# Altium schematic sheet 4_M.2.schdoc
size 431 x 309 mm; Symbol: Sheet-Symbol_A4; Device: Sheet-Symbol_A4; Company: EasyEDA.com; Drawed: EasyEDA Pro; Reviewed: EasyEDA Pro; Version: V0.1; Page Size: A4; @Project Name: CM4-Nvme-NAS-main; @Page Count: 6; @Update Date: 2023-05-19; @Create Date: 2023-04-28; @Schematic Name: RaspberryPiNVMeNAS; Part Number: JLCPCB-002; @Page No: 3; @Page Name: M.2
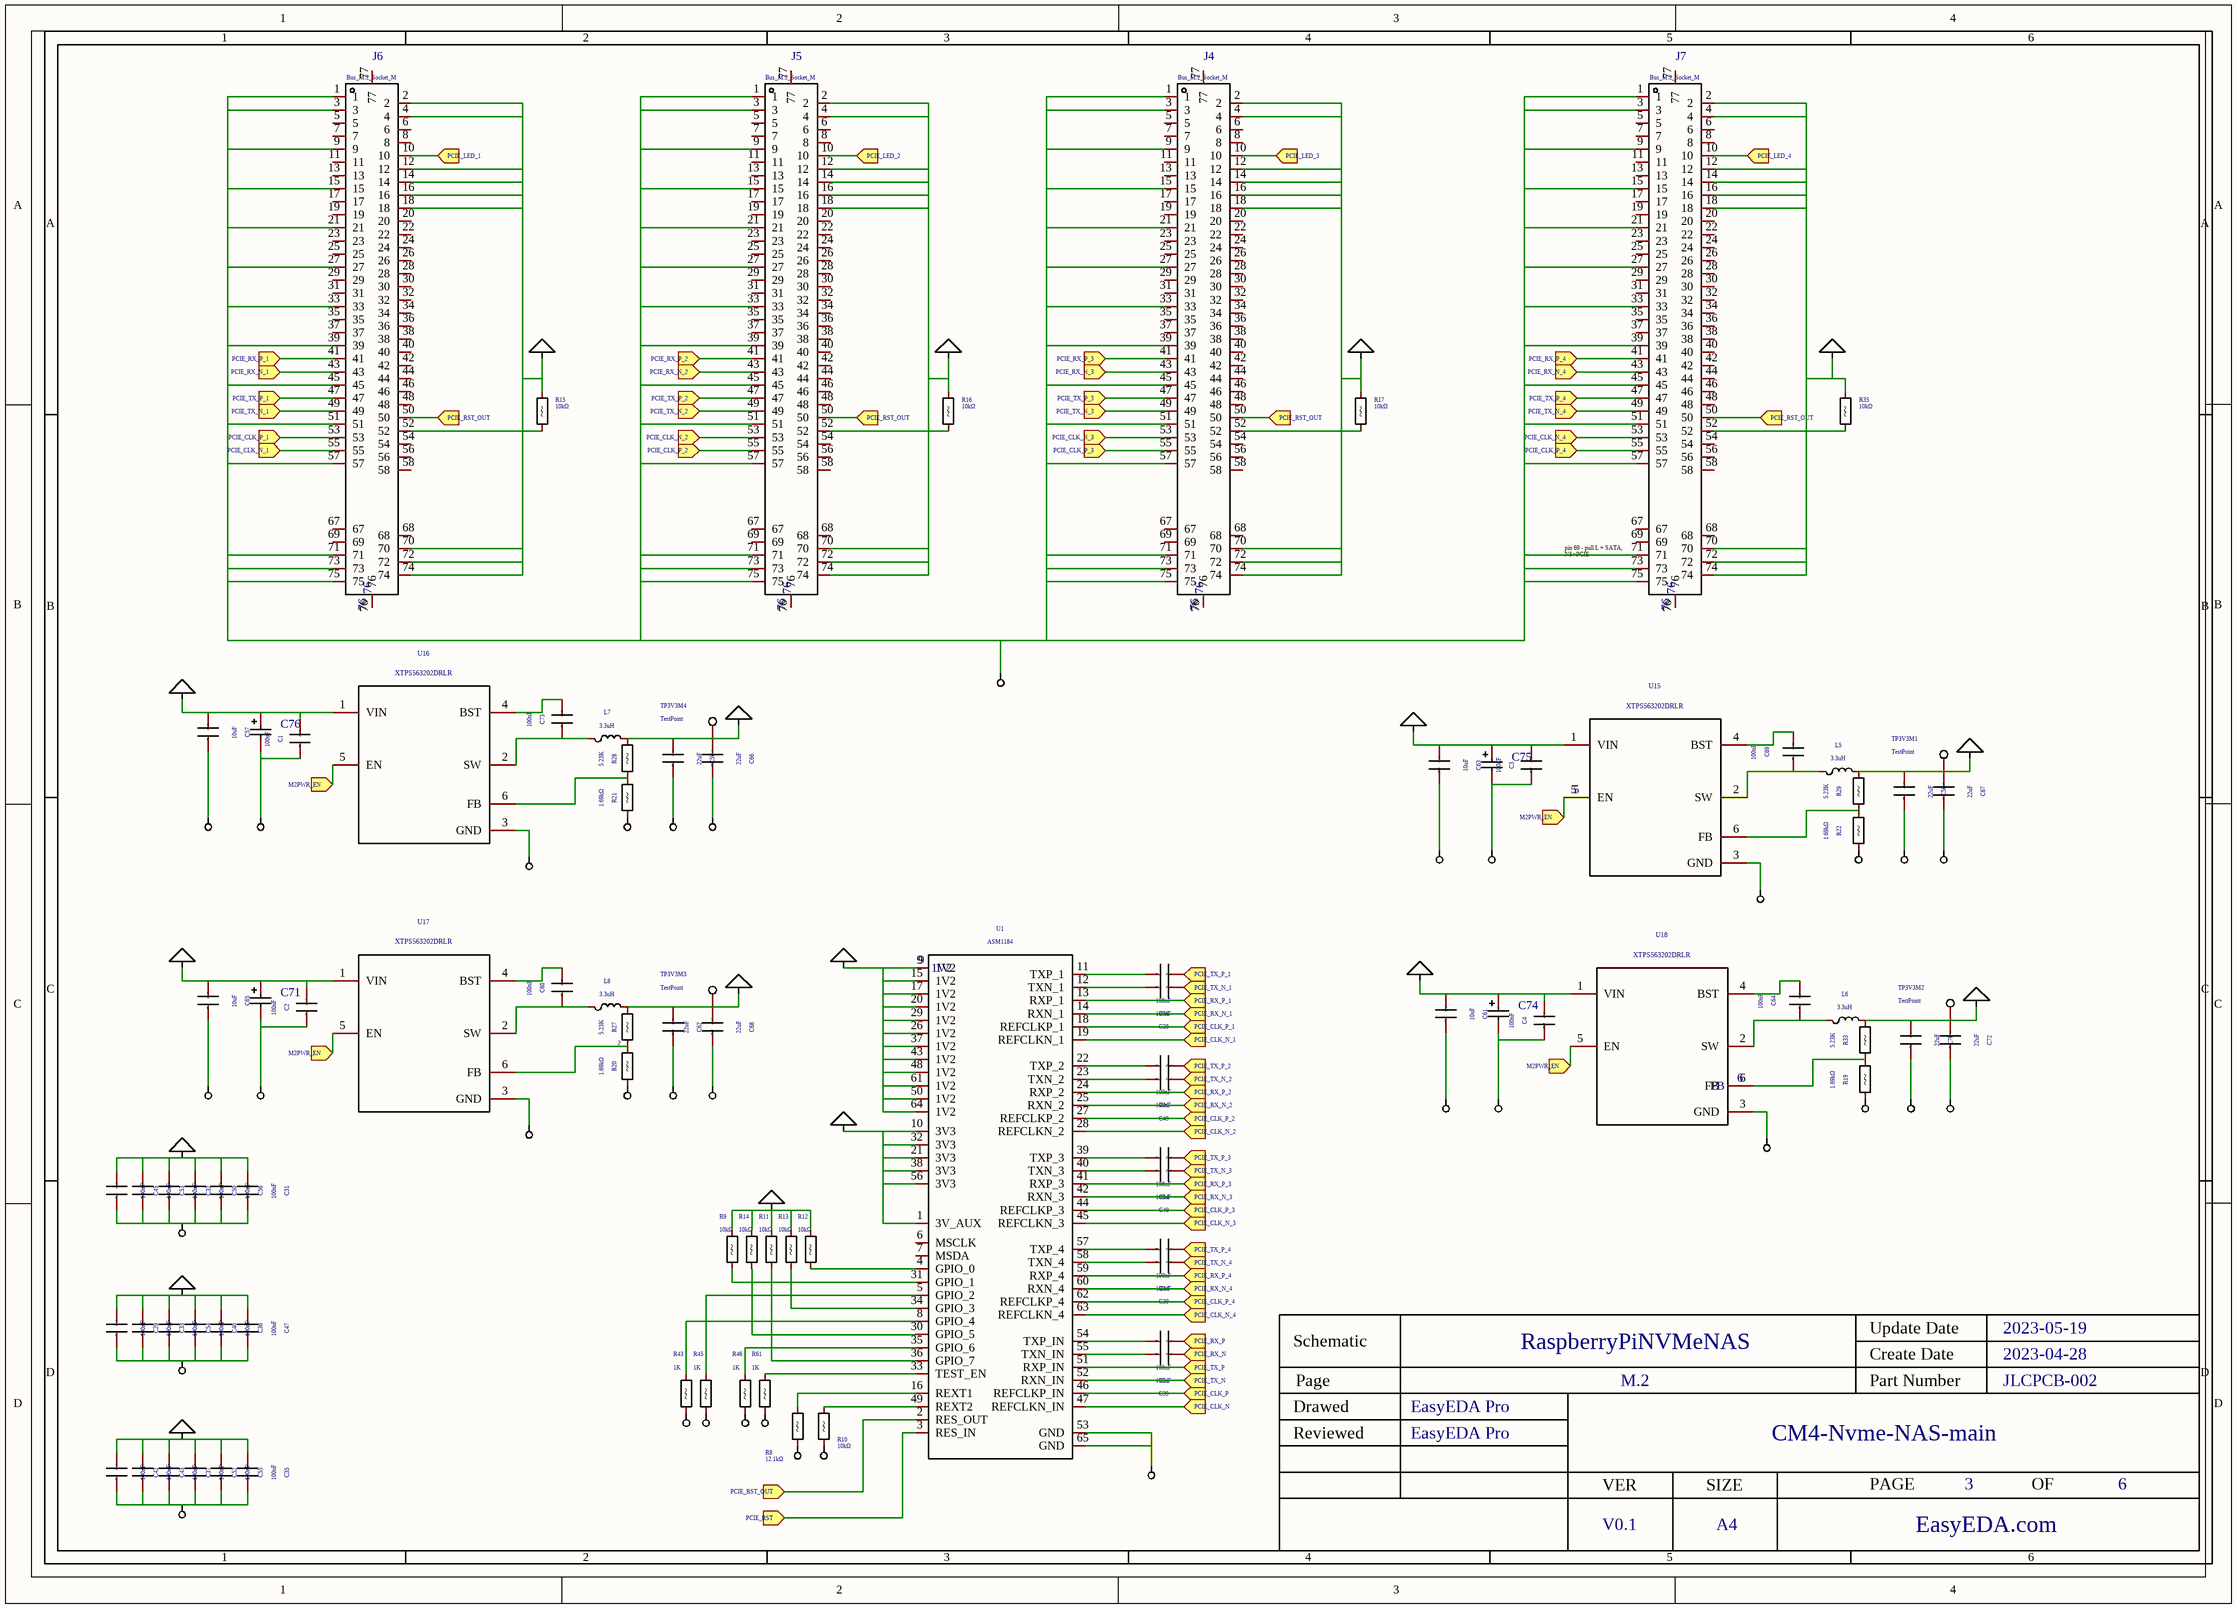
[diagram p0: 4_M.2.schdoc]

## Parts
C1  100nF  [C0402]
C2  100nF  [C0402]
C3  100nF  [C0402]
C4  100nF  [C0402]
C29  100nF  [C0402]
C30  100nF  [C0402]
C31  100nF  [C0402]
C32  100nF  [C0402]
C33  100nF  [C0402]
C34  100nF  [C0402]
C35  100nF  [C0402]
C36  100nF  [C0402]
C37  100nF  [C0402]
C38  100nF  [C0402]
C39  100nF  [C0402]
C40  100nF  [C0402]
C41  100nF  [C0402]
C42  100nF  [C0402]
C43  100nF  [C0402]
C44  100nF  [C0402]
C45  100nF  [C0402]
C46  100nF  [C0402]
C47  100nF  [C0402]
C48  100nF  [C0402]
C49  100nF  [C0402]
C50  100nF  [C0402]
C51  100nF  [C0402]
C52  100nF  [C0402]
C53  100nF  [C0402]
C54  100nF  [C0402]
C55  100nF  [C0402]
C56  100nF  [C0402]
C57  10uF  [C0805]
C58  22uF  [C0805]
C59  22uF  [C0805]
C60  100nF  [C0402]
C61  10uF  [C0805]
C62  22uF  [C0805]
C63  10uF  [C0805]
C64  100nF  [C0402]
C65  10uF  [C0805]
C66  22uF  [C0805]
C67  22uF  [C0805]
C68  22uF  [C0805]
C69  100nF  [C0402]
C70  22uF  [C0805]
C71  TAJA106K016RNJ  [CAP-SMD_L3.2-W1.6-RD-C7171]  (value not drawn)
C72  22uF  [C0805]
C73  100nF  [C0402]
C74  TAJA106K016RNJ  [CAP-SMD_L3.2-W1.6-RD-C7171]  (value not drawn)
C75  TAJA106K016RNJ  [CAP-SMD_L3.2-W1.6-RD-C7171]  (value not drawn)
C76  TAJA106K016RNJ  [CAP-SMD_L3.2-W1.6-RD-C7171]  (value not drawn)
J4  value Bus_M.2_Socket_M  NAME: 76  [PCIE-SMD_75P-P0.50_1-2199230-5]  (hidden comment: 1-2199230-5)
J5  value Bus_M.2_Socket_M  NAME: 76  [PCIE-SMD_75P-P0.50_1-2199230-5]  (hidden comment: 1-2199230-5)
J6  value Bus_M.2_Socket_M  NAME: 76  [PCIE-SMD_75P-P0.50_1-2199230-5]  (hidden comment: 1-2199230-5)
J7  value Bus_M.2_Socket_M  NAME: 76  [PCIE-SMD_75P-P0.50_1-2199230-5]  (hidden comment: 1-2199230-5)
L5  value 3.3uH  [Inductor_SMD:L_Vishay_IHLP-1212]  (hidden comment: Device_L)
L6  value 3.3uH  [Inductor_SMD:L_Vishay_IHLP-1212]  (hidden comment: Device_L)
L7  value 3.3uH  [Inductor_SMD:L_Vishay_IHLP-1212]  (hidden comment: Device_L)
L8  value 3.3uH  [Inductor_SMD:L_Vishay_IHLP-1212]  (hidden comment: Device_L)
R8  12.1kΩ  [R0402]
R9  10kΩ  [R0402]
R10  10kΩ  [R0402]
R11  10kΩ  [R0402]
R12  10kΩ  [R0402]
R13  10kΩ  [R0402]
R14  10kΩ  [R0402]
R15  10kΩ  [R0402]
R16  10kΩ  [R0402]
R17  10kΩ  [R0402]
R19  1.69kΩ  [R0402]
R20  1.69kΩ  [R0402]
R21  1.69kΩ  [R0402]
R22  1.69kΩ  [R0402]
R27  value 5.23K  NAME: ~  [Resistor_SMD:R_0402_1005Metric]  (hidden comment: Device_R)
R28  value 5.23K  [Resistor_SMD:R_0402_1005Metric]  (hidden comment: Device_R)
R29  value 5.23K  [Resistor_SMD:R_0402_1005Metric]  (hidden comment: Device_R)
R33  value 5.23K  [Resistor_SMD:R_0402_1005Metric]  (hidden comment: Device_R)
R35  10kΩ  [R0402]
R43  value 1K  [Resistor_SMD:R_0402_1005Metric]  (hidden comment: Device_R)
R45  value 1K  [Resistor_SMD:R_0402_1005Metric]  (hidden comment: Device_R)
R46  value 1K  [Resistor_SMD:R_0402_1005Metric]  (hidden comment: Device_R)
R61  value 1K  [Resistor_SMD:R_0402_1005Metric]  (hidden comment: Device_R)
TP3V3M1  value TestPoint  [TestPoint:TestPoint_Pad_D1.0mm]  (hidden comment: Connector_TestPoint)
TP3V3M2  value TestPoint  [TestPoint:TestPoint_Pad_D1.0mm]  (hidden comment: Connector_TestPoint)
TP3V3M3  value TestPoint  [TestPoint:TestPoint_Pad_D1.0mm]  (hidden comment: Connector_TestPoint)
TP3V3M4  value TestPoint  [TestPoint:TestPoint_Pad_D1.0mm]  (hidden comment: Connector_TestPoint)
U1  value ASM1184  NAME: 1V2  NUMBER: 9  [Package_DFN_QFN:QFN-64-1EP_9x9mm_P0.5mm_EP5.2x5.2mm]  (hidden comment: ASM1184_ASM1184)
U15  value XTPS563202DRLR  NUMBER: 5  [SOT-563-6_L1.6-W1.2-P0.5-LS1.6-BR]  (hidden comment: TPS563202DRLR)
U16  value XTPS563202DRLR  [SOT-563-6_L1.6-W1.2-P0.5-LS1.6-BR]  (hidden comment: TPS563202DRLR)
U17  value XTPS563202DRLR  [SOT-563-6_L1.6-W1.2-P0.5-LS1.6-BR]  (hidden comment: TPS563202DRLR)
U18  value XTPS563202DRLR  NAME: FB  NUMBER: 6  [SOT-563-6_L1.6-W1.2-P0.5-LS1.6-BR]  (hidden comment: TPS563202DRLR)

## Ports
M2PWR_EN (in), PCIE_CLK_N (in), PCIE_CLK_N_1 (in), PCIE_CLK_N_2 (in), PCIE_CLK_N_3 (in), PCIE_CLK_N_4 (in), PCIE_CLK_P (in), PCIE_CLK_P_1 (in), PCIE_CLK_P_2 (in), PCIE_CLK_P_3 (in), PCIE_CLK_P_4 (in), PCIE_LED_1 (in), PCIE_LED_2 (in), PCIE_LED_3 (in), PCIE_LED_4 (in), PCIE_RST (in), PCIE_RST_OUT (in), PCIE_RX_N (in), PCIE_RX_N_1 (in), PCIE_RX_N_2 (in), PCIE_RX_N_3 (in), PCIE_RX_N_4 (in), PCIE_RX_P (in), PCIE_RX_P_1 (in), PCIE_RX_P_2 (in), PCIE_RX_P_3 (in), PCIE_RX_P_4 (in), PCIE_TX_N (in), PCIE_TX_N_1 (in), PCIE_TX_N_2 (in), PCIE_TX_N_3 (in), PCIE_TX_N_4 (in), PCIE_TX_P (in), PCIE_TX_P_1 (in), PCIE_TX_P_2 (in), PCIE_TX_P_3 (in), PCIE_TX_P_4 (in)

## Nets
+1V2: U1.9(1V2) U1.15(1V2) U1.17(1V2) U1.20(1V2) U1.26(1V2) U1.29(1V2) U1.37(1V2) U1.43(1V2) U1.48(1V2) U1.50(1V2) U1.61(1V2) U1.64(1V2)
+3.3VA: U1.1(3V_AUX) U1.10(3V3) U1.21(3V3) U1.32(3V3) U1.38(3V3) U1.56(3V3)
+12V: C4.1 C61.1 C74.1 U18.1(VIN)
GND: C1.2 C2.2 C4.2 C57.2 C61.2 C62.2 C65.2 C66.2 C68.2 C70.2 C71.2 C72.2 C74.2 C76.2 R8.2 R10.2 R19.2 R20.2 R43.2 R45.2 R46.2 R61.2 U15.3(GND) U16.3(GND) U17.3(GND) U18.3(GND)
POWER_3.3M1: C58.1 C67.1 J6.2 J6.4 J6.12 J6.14 J6.16 J6.18 J6.70 J6.72 J6.74 L5.2 R15.1 R29.1 TP3V3M1.1
POWER_3.3M2: C70.1 C72.1 J5.2 J5.4 J5.12 J5.14 J5.16 J5.18 J5.70 J5.72 J5.74 L6.2 R16.1 R33.1 TP3V3M2.1
POWER_3.3M3: C62.1 C68.1 J4.2 J4.4 J4.12 J4.14 J4.16 J4.18 J4.70 J4.72 J4.74 L8.2 R17.1 R27.1 TP3V3M3.1
POWER_3.3M4: C59.1 C66.1 J7.2 J7.4 J7.12 J7.14 J7.16 J7.18 J7.70 J7.72 J7.74 L7.2 R28.1 R35.1 TP3V3M4.1
POWER_+1V2: C29.1 C31.1 C32.1 C33.1 C36.1 C40.1 C45.1 C47.1 C50.1 C53.1 C54.1 C56.1
POWER_+3.3VA: C35.1 C37.1 C42.1 C43.1 C52.1 C55.1 R9.1 R11.1 R12.1 R13.1 R14.1
POWER_+12V: C1.1 C2.1 C3.1 C57.1 C63.1 C65.1 C71.1 C75.1 C76.1 U15.1(VIN) U16.1(VIN) U17.1(VIN)
POWER_GND: C3.2 C29.2 C31.2 C32.2 C33.2 C35.2 C36.2 C37.2 C40.2 C42.2 C43.2 C45.2 C47.2 C50.2 C52.2 C53.2 C54.2 C55.2 C56.2 C58.2 C59.2 C63.2 C67.2 C75.2 J4.1 J4.3 J4.9 J4.15 J4.21 J4.27 J4.33 J4.39 J4.45 J4.51 J4.57 J4.71 J4.73 J4.75 J5.1 J5.3 J5.9 J5.15 J5.21 J5.27 J5.33 J5.39 J5.45 J5.51 J5.57 J5.71 J5.73 J5.75 J6.1 J6.3 J6.9 J6.15 J6.21 J6.27 J6.33 J6.39 J6.45 J6.51 J6.57 J6.71 J6.73 J6.75 J7.1 J7.3 J7.9 J7.15 J7.21 J7.27 J7.33 J7.39 J7.45 J7.51 J7.57 J7.71 J7.73 J7.75 R21.2 R22.2 U1.53(GND) U1.65(GND)
M2PWR_EN: U15.5(EN) U16.5(EN) U17.5(EN) U18.5(EN) ; port M2PWR_EN
PCIE_CLK_N: U1.47(REFCLKN_IN) ; port PCIE_CLK_N
PCIE_CLK_N_1: J6.55 U1.19(REFCLKN_1) ; port PCIE_CLK_N_1
PCIE_CLK_N_2: J5.53 U1.28(REFCLKN_2) ; port PCIE_CLK_N_2
PCIE_CLK_N_3: J4.53 U1.45(REFCLKN_3) ; port PCIE_CLK_N_3
PCIE_CLK_N_4: J7.53 U1.63(REFCLKN_4) ; port PCIE_CLK_N_4
PCIE_CLK_P: U1.46(REFCLKP_IN) ; port PCIE_CLK_P
PCIE_CLK_P_1: J6.53 U1.18(REFCLKP_1) ; port PCIE_CLK_P_1
PCIE_CLK_P_2: J5.55 U1.27(REFCLKP_2) ; port PCIE_CLK_P_2
PCIE_CLK_P_3: J4.55 U1.44(REFCLKP_3) ; port PCIE_CLK_P_3
PCIE_CLK_P_4: J7.55 U1.62(REFCLKP_4) ; port PCIE_CLK_P_4
PCIE_LED_1: J6.10 ; port PCIE_LED_1
PCIE_LED_2: J5.10 ; port PCIE_LED_2
PCIE_LED_3: J4.10 ; port PCIE_LED_3
PCIE_LED_4: J7.10 ; port PCIE_LED_4
PCIE_RST: U1.3(RES_IN) ; port PCIE_RST
PCIE_RST_OUT: J4.50 J5.50 J6.50 J7.50 U1.2(RES_OUT) ; port PCIE_RST_OUT
PCIE_RX_N: C39.1 ; port PCIE_RX_N
PCIE_RX_N_1: J6.43 U1.14(RXN_1) ; port PCIE_RX_N_1
PCIE_RX_N_2: J5.43 U1.25(RXN_2) ; port PCIE_RX_N_2
PCIE_RX_N_3: J4.43 U1.42(RXN_3) ; port PCIE_RX_N_3
PCIE_RX_N_4: J7.43 U1.60(RXN_4) ; port PCIE_RX_N_4
PCIE_RX_P: C51.1 ; port PCIE_RX_P
PCIE_RX_P_1: J6.41 U1.13(RXP_1) ; port PCIE_RX_P_1
PCIE_RX_P_2: J5.41 U1.24(RXP_2) ; port PCIE_RX_P_2
PCIE_RX_P_3: J4.41 U1.41(RXP_3) ; port PCIE_RX_P_3
PCIE_RX_P_4: J7.41 U1.59(RXP_4) ; port PCIE_RX_P_4
PCIE_TX_N: U1.52(RXN_IN) ; port PCIE_TX_N
PCIE_TX_N_1: C38.1 J6.49 ; port PCIE_TX_N_1
PCIE_TX_N_2: C49.1 J5.49 ; port PCIE_TX_N_2
PCIE_TX_N_3: C48.1 J4.49 ; port PCIE_TX_N_3
PCIE_TX_N_4: C30.1 J7.49 ; port PCIE_TX_N_4
PCIE_TX_P: U1.51(RXP_IN) ; port PCIE_TX_P
PCIE_TX_P_1: C46.1 J6.47 ; port PCIE_TX_P_1
PCIE_TX_P_2: C41.1 J5.47 ; port PCIE_TX_P_2
PCIE_TX_P_3: C34.1 J4.47 ; port PCIE_TX_P_3
PCIE_TX_P_4: C44.1 J7.47 ; port PCIE_TX_P_4
NetC30_2: C30.2 U1.58(TXN_4)
NetC34_2: C34.2 U1.39(TXP_3)
NetC38_2: C38.2 U1.12(TXN_1)
NetC39_2: C39.2 U1.55(TXN_IN)
NetC41_2: C41.2 U1.22(TXP_2)
NetC44_2: C44.2 U1.57(TXP_4)
NetC46_2: C46.2 U1.11(TXP_1)
NetC48_2: C48.2 U1.40(TXN_3)
NetC49_2: C49.2 U1.23(TXN_2)
NetC51_2: C51.2 U1.54(TXP_IN)
NetC60_1: C60.1 U17.4(BST)
NetC60_2: C60.2 L8.1 U17.2(SW)
NetC64_1: C64.1 U18.4(BST)
NetC64_2: C64.2 L6.1 U18.2(SW)
NetC69_1: C69.1 U15.4(BST)
NetC69_2: C69.2 L5.1 U15.2(SW)
NetC73_1: C73.1 U16.4(BST)
NetC73_2: C73.2 L7.1 U16.2(SW)
NetJ4_52: J4.52 R17.2
NetJ5_52: J5.52 R16.2
NetJ6_52: J6.52 R15.2
NetJ7_52: J7.52 R35.2
NetR8_1: R8.1 U1.16(REXT1)
NetR9_2: R9.2 U1.31(GPIO_1)
NetR10_1: R10.1 U1.49(REXT2)
NetR11_2: R11.2 U1.36(GPIO_7)
NetR12_2: R12.2 U1.4(GPIO_0)
NetR13_2: R13.2 U1.34(GPIO_3)
NetR14_2: R14.2 U1.30(GPIO_5)
NetR19_1: R19.1 R33.2 U18.6(FB)
NetR20_1: R20.1 R27.2 U17.6(FB)
NetR21_1: R21.1 R28.2 U16.6(FB)
NetR22_1: R22.1 R29.2 U15.6(FB)
NetR43_1: R43.1 U1.8(GPIO_4)
NetR45_1: R45.1 U1.5(GPIO_2)
NetR46_1: R46.1 U1.35(GPIO_6)
NetR61_1: R61.1 U1.33(TEST_EN)

Not connected (* = marked no-connect by the designer): J4 5 6 7 8 11 13 17 19 20 22 23 24 25 26 28 29 30 31 32 34 35 36 37 38 40 42 44 46 48 54 56 58 67 68 69 76 77; J5 5 6 7 8 11 13 17 19 20 22 23 24 25 26 28 29 30 31 32 34 35 36 37 38 40 42 44 46 48 54 56 58 67 68 69 76 77; J6 5 6 7 8 11 13 17 19 20 22 23 24 25 26 28 29 30 31 32 34 35 36 37 38 40 42 44 46 48 54 56 58 67 68 69 76 77; J7 5 6 7 8 11 13 17 19 20 22 23 24 25 26 28 29 30 31 32 34 35 36 37 38 40 42 44 46 48 54 56 58 67 68 69 76 77; U1 6(MSCLK) 7(MSDA)

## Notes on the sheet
- (near J7) pin 69 - pull L = SATA,
  NS=PCIE

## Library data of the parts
C1-C4 C29-C56 C60 C64 C69 C73 = CL05B104KO5NNNC: Capacitance: Tolerance:±10% Tolerance:±10% Voltage Rated: Temperature Coefficient:; Manufacturer: SAMSUNG(三星); Add into BOM: yes; Tolerance: ±10%; Origin Footprint: C_0402_1005Metric
C57 C61 C63 C65 = CL21A106KAYNNNE_C15850: Capacitance: Tolerance:±10% Tolerance:±10% Voltage Rated: Temperature Coefficient:; Manufacturer: SAMSUNG(三星); Add into BOM: yes; Tolerance: ±10%; Origin Footprint: C_0805_2012Metric
C58 C59 C66 C67 C70 C72 = GRM21BR60J226ME39L: Capacitance: Tolerance:±20% Tolerance:±20% Voltage Rated: Temperature Coefficient:; Manufacturer: muRata(村田); Add into BOM: yes; Tolerance: ±20%; Origin Footprint: C_0805_2012Metric
C62 C68 = GRM21BR60J226ME39L: Capacitance: Tolerance:±20% Tolerance:±20% Voltage Rated: Temperature Coefficient:; Manufacturer: muRata(村田); Add into BOM: yes; Tolerance: ±20%; Origin Footprint: C_0805_2012Metric; NUMBER: 2; Pin Type: IN
C71 C74-C76 = TAJA106K016RNJ: Capacitance: Tolerance:±10% Tolerance:±10% Rated Voltage: Equivalent Series Resistance(ESR):3Ω@100kHz Operating Temperature:-55℃~+125℃ Operating Temperature:-55℃~+125℃; Manufacturer: Kyocera AVX; Name: 10uF; Add into BOM: yes; Value: 10uF; Tolerance: ±10%; Origin Footprint: C_0805_2012Metric
J4-J7 = 1-2199230-5: Connector Type:M.2 Pitch:0.5mm Number of Pins:67 Mounting Style:Surface Mount Height Above Board:4.2mm Operating Temperature Range:- Operating Temperature Range:-; Manufacturer: TE Connectivity(美国泰科); Add into BOM: yes; Connector Type: M.2; Pitch: 0.5mm; Origin Footprint: 1-2199230-6
L5-L8 = Device_L: Add into BOM: yes; Origin Footprint: L_Vishay_IHLP-1212
R8 = RC0402FR-0712K1L: Type:Thick Film Resistors Resistance: Tolerance:±1% Tolerance:±1% Power(Watts): Temperature Coefficient:±100ppm/℃ Temperature Coefficient:±100ppm/℃ Overload Voltage (Max): Operating Temperature Range:-55℃~+155℃ Operating Temperature Range:-55℃~+155℃; Manufacturer: YAGEO(国巨); Add into BOM: yes; Tolerance: ±1%; Origin Footprint: R_0402_1005Metric
R9-R17 R35 = 0402WGF1002TCE: Type:Thick Film Resistors Resistance: Tolerance:±1% Tolerance:±1% Power(Watts): Temperature Coefficient:±100ppm/℃ Temperature Coefficient:±100ppm/℃ Overload Voltage (Max): Operating Temperature Range:-55℃~+155℃ Operating Temperature Range:-55℃~+155℃; Manufacturer: UNI-ROYAL(厚声); Add into BOM: yes; Tolerance: ±1%; Origin Footprint: R_0402_1005Metric
R19-R22 = CR0402FF1691G: Type:Thick Film Resistors Resistance: Tolerance:±1% Tolerance:±1% Power(Watts): Temperature Coefficient:±200ppm/℃ Temperature Coefficient:±200ppm/℃ Overload Voltage (Max): Operating Temperature Range:-55℃~+125℃ Operating Temperature Range:-55℃~+125℃; Manufacturer: LIZ(丽智电子); Add into BOM: yes; Tolerance: ±1%; Origin Footprint: R_0402_1005Metric
R27 = Device_R: Add into BOM: yes; Origin Footprint: R_0402_1005Metric; NUMBER: 2; Pin Type: IN
R28 R29 R33 R43 R45 R46 R61 = Device_R: Add into BOM: yes; Origin Footprint: R_0402_1005Metric
TP3V3M1-TP3V3M4 = Connector_TestPoint: Add into BOM: yes; Origin Footprint: TestPoint_Pad_D1.0mm
U1 = ASM1184_ASM1184: Add into BOM: yes; Origin Footprint: QFN-64-1EP_9x9mm_P0.5mm_EP5.2x5.2mm; Pin Type: IN
U15 U18 = TPS563202DRLR: Function:Step-down type Synchronous Rectification:Yes Output Type:Adjustable Number of Outputs:1 Topology:Step-down Input Voltage:4.3V~17V Input Voltage:4.3V~17V Output Voltage:0.806V~7V Output Voltage:0.806V~7V Output Current (Max):3A Switching Frequency; Manufacturer: TI(德州仪器); Add into BOM: yes; Number of Outputs: 1; Output Current (Max): 3A; Switching Frequency: 580kHz; Pin Type: IN
U16 U17 = TPS563202DRLR: Function:Step-down type Synchronous Rectification:Yes Output Type:Adjustable Number of Outputs:1 Topology:Step-down Input Voltage:4.3V~17V Input Voltage:4.3V~17V Output Voltage:0.806V~7V Output Voltage:0.806V~7V Output Current (Max):3A Switching Frequency; Manufacturer: TI(德州仪器); Add into BOM: yes; Number of Outputs: 1; Output Current (Max): 3A; Switching Frequency: 580kHz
